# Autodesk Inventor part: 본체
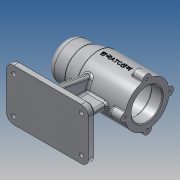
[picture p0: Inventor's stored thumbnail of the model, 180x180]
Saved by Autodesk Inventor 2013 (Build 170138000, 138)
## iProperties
Created: 2019-07
Part Number: 본체
Material: 알루미늄 6061
Document SubType Name: Modeling
Designer: Administrator
Density: 2.71 g/cm^3
Mass: 646.774 g
Surface Area: 654.083 cm^2
Volume: 238.662 cm^3
Author: Administrator
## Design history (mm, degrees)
sketch "스케치1"
  geometry: L1 (56, 0)-(-56, 0); L2 (-56, 0)-(-56, 25); L3 (-56, 25)-(-31, 25); L4 (-31, 25)-(-11, 30); L5 (-11, 30)-(56, 30); L6 (56, 30)-(56, 0); 2 further points
  constraints: 12 end point, 2 parallel, 2 perpendicular, 1 coincident, 1 horizontal, 1 midpoint
  dimensions: "d0" = 112 distance of L1.start L1.end; "d3" = 60 diameter of L5 L1; "d4" = 50 diameter of L3 L1; "d5" = 25 distance of L2.end L3.end; "d6" = 45 horizontal distance of L4.end L2.end
revolve "회전1" sketch "스케치1" stored, may be unused: angle "d7" = 90 deg
node "작업 평면1"
sketch "스케치2"
  geometry: L1 (-56, 35)-(56, 35); L2 (56, 35)-(56, -35); L3 (56, -35)-(-56, -35); L4 (-56, -35)-(-56, 35); L5 (-56, 35)-(56, -35); L6 (56, 35)-(-56, -35); 1 further point
  constraints: 12 end point, 2 midpoint, 2 parallel, 1 horizontal, 1 perpendicular
  dimensions: "d9" = 112 distance of L2.end L3.end; "d11" = 70 distance of L3.end L1.start
extrude "돌출1" join sketch "스케치2" distance "d12" = 10; taper "d13" = 0 deg
sketch "스케치5"
  geometry: L1 (-56, -25)-(-56, 25) reference; L2 (-56, 25)-(-31, 25) reference; L3 (-31, 25)-(-11, 30) reference; L4 (-11, 30)-(56, 30) reference; L5 (56, 30)-(56, -30) reference; L6 (56, -30)-(-11, -30) reference; L7 (-11, -30)-(-31, -25) reference; L8 (-31, -25)-(-56, -25) reference; L9 (56, -70)-(56, -80) reference; L10 (56, -80)-(-56, -80) reference; L11 (-56, -80)-(-56, -70) reference; L12 (-56, -70)-(56, -70) reference; L13 (56, 0)-(-50, 0); L14 (56, 0)-(56, 21); L15 (56, 21)-(41, 21); L16 (41, 21)-(41, 24); L17 (41, 24)-(-13, 24); L18 (-13, 24)-(-13, 21); L19 (-13, 21)-(-25, 21); L20 (-25, 21)-(-25, 17.5); L21 (-25, 17.5)-(-43, 17.5); L22 (-43, 17.5)-(-43, 16); L23 (-43, 16)-(-47, 16); L24 (-47, 16)-(-47, 10.5); L25 (-47, 10.5)-(-50, 10.5); L26 (-50, 10.5)-(-50, 0); 1 further point
  constraints: 28 end point, 10 parallel, 2 perpendicular, 1 collinear, 1 horizontal, 1 midpoint
  dimensions: "d23" = 15 distance of L14.end L15.end; "d25" = 54 distance of L16.end L17.end; "d26" = 12 distance of L18.end L19.end; "d27" = 18 distance of L20.end L21.end; "d28" = 4 distance of L22.end L23.end; "d29" = 3 distance of L24.end L25.end; "d30" = 42 diameter of L15 L13; "d31" = 48 diameter of L17 L13; "d32" = 42 diameter of L19 L13; "d33" = 35 diameter of L21 L13; "d34" = 32 diameter of L23 L13; "d35" = 21 diameter of L25 L13
revolve "회전2" sketch "스케치5" stored, may be unused: angle "d36" = 90 deg
sketch "스케치6"
  geometry: C1 r 6 at (-0.293, 29.999); 2 further points
  constraints: 1 centre point, 4 other
  dimensions: "d37" = 12 diameter of C1
extrude "돌출2" join sketch "스케치6" distance "d39" = 16; taper "d40" = 0 deg
sketch "스케치7"
  geometry: A1 r 6 centre (0, 0) between (5.97, -0.6) and (-5.97, -0.6) reference; 1 further point
  constraints: 1 coincident
hole "구멍1" sketch "스케치7" at (0, 0) diameter "d41" = 3.242; stored, may be unused: countersink angle "d45" = 90 deg, drill point angle "d47" = 118 deg; dims "d42" = 8, "d43" = 4, "d44" = 2, "d46" = 11
fillet "모깎기1" dims "d51" = 10
fillet "모깎기2" dims "d52" = 3
fillet "모깎기3" dims "d53" = 1
chamfer "모따기1" distance "d54" = 3; stored, may be unused: second distance "d55" = 2, angle "d56" = 45 deg
sketch "스케치8"
  geometry: A1 r 7 centre (-46, 25) between (-46, 32) and (-53, 25) reference; 2 further points
  constraints: 1 coincident
hole "구멍2" sketch "스케치8" at (-46, 25) diameter "d57" = 6; stored, may be unused: countersink angle "d61" = 90 deg, drill point angle "d63" = 118 deg; dims "d58" = 8, "d59" = 4, "d60" = 2, "d62" = 11
fillet "모깎기4" dims "d64" = 0.3
fillet "모깎기5" dims "d65" = 3
fillet "모깎기6" dims "d66" = 3
chamfer "모따기2" distance "d67" = 1; stored, may be unused: second distance "d68" = 2, angle "d69" = 45 deg
sketch "스케치9"
  geometry: L1 (45, 28.404)-(56, 28.404) reference; L2 (56, 28.404)-(56, 22) reference; L3 (56, 22)-(55, 21) reference; L4 (55, 21)-(41, 21) reference; L5 (38, 24)-(-10, 24) reference; L6 (-13, 21)-(-24.7, 21) reference; L7 (-25, 20.7)-(-25, 17.5) reference; L8 (-25, 17.5)-(-42.7, 17.5) reference; L9 (-43, 17.2)-(-43, 16) reference; L10 (-43, 16)-(-46.7, 16) reference; L11 (-47, 15.7)-(-47, 10.5) reference; L12 (-50, 7.5)-(-50, -7.5) reference; L13 (-47, -10.5)-(-47, -15.7) reference; L14 (-46.7, -16)-(-43, -16) reference; L15 (-43, -16)-(-43, -17.2) reference; L16 (-42.7, -17.5)-(-25, -17.5) reference; L17 (-25, -17.5)-(-25, -20.7) reference; L18 (-24.7, -21)-(-13, -21) reference; L19 (-10, -24)-(38, -24) reference; L20 (41, -21)-(55, -21) reference; L21 (55, -21)-(56, -22) reference; L22 (56, -22)-(56, -28.404) reference; L23 (56, -28.404)-(45, -28.404) reference; L24 (45, -31.593)-(56, -31.593) reference; L25 (56, -31.593)-(56, -35.991) reference; L26 (56, -35.991)-(43, -35.991) reference; L27 (40, -32.984)-(40, -31) reference; L28 (39, -30)-(-10.631, -30) reference; L29 (-11.358, -29.91)-(-30.642, -25.09) reference; L30 (-31.369, -25)-(-46, -25) reference; L31 (-56, -15)-(-56, 15) reference; L32 (-46, 25)-(-31.369, 25) reference; L33 (-30.642, 25.09)-(-11.358, 29.91) reference; L34 (-10.631, 30)-(39, 30) reference; L35 (40, 31)-(40, 32.984) reference; L36 (43, 35.991)-(56, 35.991) reference; L37 (56, 35.991)-(56, 31.593) reference; L38 (56, 31.593)-(45, 31.593) reference; L39 (-56, -73)-(-53, -70) reference; L40 (-53, -70)-(53, -70) reference; L41 (53, -70)-(56, -73) reference; L42 (56, -73)-(56, -80) reference; L43 (56, -80)-(-56, -80) reference; L44 (-56, -80)-(-56, -73) reference; L45 (-46, -70)-(46, -70) reference; L46 (31, -70)-(31, -25.443); L47 (-36, -70)-(31, -70); L48 (-19.783, -25.443)-(-36, -70); L49 (-19.783, -25.443)-(31, -25.443); A1 r 3 centre (38, 21) between (41, 21) and (38, 24) reference; A2 r 3 centre (-10, 21) between (-10, 24) and (-13, 21) reference; A3 r 0.3 centre (-24.7, 20.7) between (-24.7, 21) and (-25, 20.7) reference; A4 r 0.3 centre (-42.7, 17.2) between (-42.7, 17.5) and (-43, 17.2) reference; A5 r 0.3 centre (-46.7, 15.7) between (-46.7, 16) and (-47, 15.7) reference; A6 r 3 centre (-47, 7.5) between (-47, 10.5) and (-50, 7.5) reference; A7 r 3 centre (-47, -7.5) between (-50, -7.5) and (-47, -10.5) reference; A8 r 0.3 centre (-46.7, -15.7) between (-47, -15.7) and (-46.7, -16) reference; A9 r 0.3 centre (-42.7, -17.2) between (-43, -17.2) and (-42.7, -17.5) reference; A10 r 0.3 centre (-24.7, -20.7) between (-25, -20.7) and (-24.7, -21) reference; A11 r 3 centre (-10, -21) between (-13, -21) and (-10, -24) reference; A12 r 3 centre (38, -21) between (38, -24) and (41, -21) reference; A13 r 1 centre (39, -31) between (40, -31) and (39, -30) reference; A14 r 3 centre (-10.631, -27) between (-11.358, -29.91) and (-10.631, -30) reference; A15 r 3 centre (-31.369, -28) between (-30.642, -25.09) and (-31.369, -25) reference; A16 r 10 centre (-46, -15) between (-56, -15) and (-46, -25) reference; A17 r 10 centre (-46, 15) between (-46, 25) and (-56, 15) reference; A18 r 3 centre (-31.369, 28) between (-31.369, 25) and (-30.642, 25.09) reference; A19 r 3 centre (-10.631, 27) between (-10.631, 30) and (-11.358, 29.91) reference; A20 r 1 centre (39, 31) between (39, 30) and (40, 31) reference; 2 further points
  constraints: 8 end point, 3 point on line, 2 vertical alignment, 1 midpoint, 1 parallel, 1 perpendicular, 2 other
  dimensions: "d72" = 25 horizontal distance of L42.end L46.start; "d81" = 20 horizontal distance of L48.end L43.end; "d82" = 110 deg angle of L48 L40
extrude "돌출3" join sketch "스케치9" stored distance "d73" = 8; taper "d74" = 0 deg
sketch "스케치10"
  geometry: L1 (-22.666, 19.654)-(-70, 28); L2 (-70, 28)-(-70, 22) reference; L3 (-80, 35)-(-73, 35) reference; L4 (-70, 32)-(-70, 25) reference; L5 (-70, 25)-(-70, -25) reference; L6 (-27.5, 4)-(-70, 4) reference; A1 r 30 centre (0, 0) between (-29.732, -4) and (-29.732, 4) reference; 1 further point
  constraints: 2 end point, 1 point on circle, 1 point on line
  dimensions: "d75" = 7 distance from line of L1.end L3; "d76" = 100 deg angle of L1 L4
extrude "돌출4" join sketch "스케치10" stored distance "d77" = 8; taper "d78" = 0 deg
fillet "모깎기7" dims "d79" = 3
fillet "모깎기8" dims "d80" = 3
node "작업 평면2"
sketch "스케치11"
  geometry: L1 (33.5, 35.999)-(33.5, 30.111) reference; 3 further points
  constraints: 1 horizontal alignment, 1 other
  dimensions: "d83" = 42 distance from line of L1 point (-8.5, 0)
feature "엠보싱1" sketch "스케치11" dims "d84" = 0.5, "d85" = 0
node "솔리드1"
pattern_circular "원형 패턴1" dims angle "d49" = 360 deg
mirror "대칭1"
mirror "대칭2"
mirror "대칭3"
node "절단 모서리 투영2"
node "절단 모서리 투영3"
